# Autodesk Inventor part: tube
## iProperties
Author: Administrator
Created: 2001-03
Part Number: tube
Document SubType Name: Modeling
Designer: Administrator
Control State: 0
Master: False
Checked Out: False
PropertySet Name: Design Tracking Control
Shininess: 20.0
PropertySet Name: _Private Model Information
Density: 0.0
Volumn: 0.0
Area: 0.0
PropertySet Name: Model Information
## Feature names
1. Sweep1
2. Shell1
